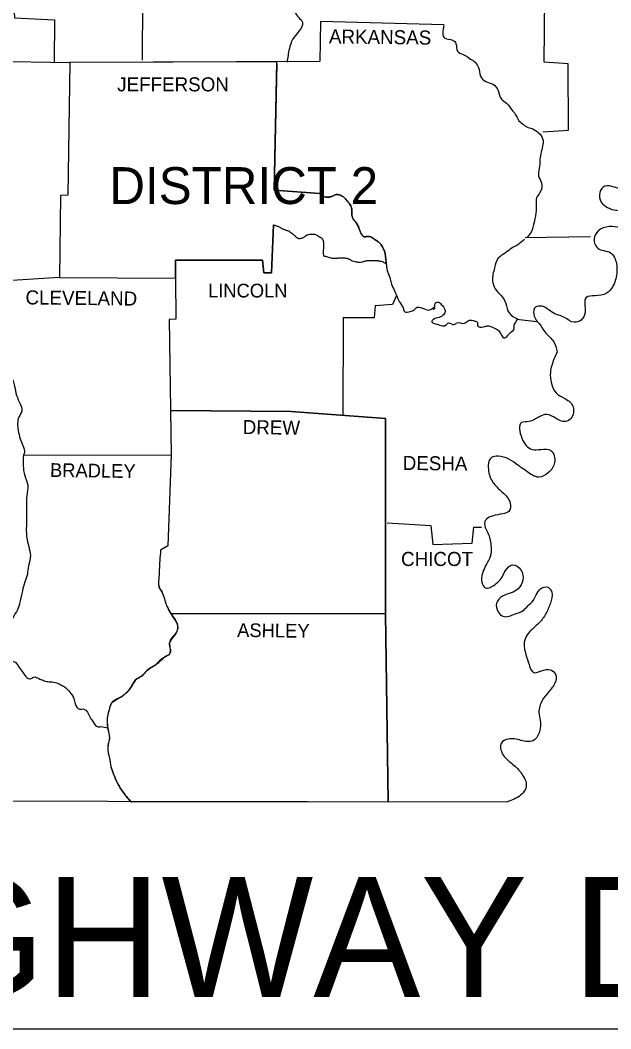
# Model space of a CAD drawing. Extents: x -2512 to 3792, y -435 to 2624.
# Drawn here: x 2982.2 to 3159.1, y 1364.9 to 1667 of the extents above; entities that cross this region are included whole.
import ezdxf

# ---------------------------------------------------------------- set-up
doc = ezdxf.new("R2010")
doc.units = 0
for name, color, linetype in [('1', 7, 'Continuous'), ('2', 7, 'Continuous'), ('3', 7, 'Continuous'), ('S_MISC_BOUNDARY', 7, 'Continuous')]:
    doc.layers.add(name, color=color, linetype=linetype)

msp = doc.modelspace()

# ---------------------------------------------------------------- linework, layer by layer
at = {"layer": '1'}
msp.add_line((3133.42, 1601.94), (3152.99, 1602.24), dxfattribs=at)
for points in [[(3007.21, 1732.56), (3012.88, 1732.17), (3012.98, 1694.79), (3007.89, 1673.56), (3018.75, 1673.07), (3018.66, 1655.07)], [(3138.71, 1633.54), (3146.34, 1634.03), (3146.24, 1653.9), (3139.1, 1654.38), (3139.49, 1693.23), (3133.33, 1694.11), (3133.13, 1720.23), (3216.59, 1720.82)], [(2931.68, 1708.1), (2942.63, 1707.41), (2942.24, 1695.18), (2955.06, 1694.69), (2955.26, 1684.03), (2961.32, 1683.54), (2961.32, 1681.68), (2967, 1681.29), (2967.19, 1674.44), (2980.11, 1674.44), (2980.5, 1667.69), (2992.44, 1667.1), (2992.34, 1654.38)], [(3109.06, 1665.64), (3072.08, 1666.61), (3071.88, 1654.58), (2997.03, 1654.29)], [(2940.68, 1641.37), (2946.16, 1642.15), (2946.55, 1645.48), (2949.78, 1646.07), (2949.97, 1648.02), (2972.77, 1648.71), (2973.65, 1654.68), (2997.03, 1654.29)], [(2997.03, 1654.09), (2996.45, 1614.56), (2994.2, 1614.47), (2993.9, 1589.91)], [(3059.06, 1653.99), (3058.28, 1616.13), (3071.88, 1615.05)], [(3057.99, 1605.66), (3057.4, 1591.28), (3055.15, 1591.28), (3054.76, 1595.09), (3028.73, 1595.09), (3028.73, 1589.61)], [(2993.9, 1589.91), (2979.62, 1589.03)], [(2993.9, 1589.91), (3028.54, 1589.71)], [(3028.73, 1589.71), (3028.83, 1577.48), (3026.78, 1577.38), (3027.36, 1536.78)], [(3094.87, 1584.53), (3093.7, 1581.88), (3088.51, 1581.4), (3088.22, 1577.87), (3078.93, 1577.87), (3078.83, 1548.62)], [(3105.83, 1580.22), (3106.13, 1580.51), (3106.42, 1580.81), (3106.42, 1580.81)], [(3027.07, 1550.09), (3063.37, 1549.79), (3091.55, 1547.64)], [(3091.55, 1547.64), (3091.55, 1489.13), (3092.33, 1432.87)], [(2983.14, 1536.68), (3027.36, 1536.78)], [(3027.36, 1536.78), (3026.39, 1509.58), (3024.23, 1508.21)], [(3092.04, 1516.43), (3105.15, 1515.65), (3105.73, 1509.97), (3117.57, 1510.36), (3118.06, 1515.16), (3120.31, 1515.16)], [(2769.26, 1512.61), (2769.46, 1433.46), (3128.04, 1432.87)], [(3027.95, 1489.23), (3091.55, 1489.23)]]:
    msp.add_lwpolyline(points, dxfattribs=at)
for points in [[(3210.42, 1697.14), (3208.17, 1694.3), (3204.85, 1696.06), (3204.85, 1698.41), (3205.34, 1700.86), (3204.16, 1702.42), (3202.11, 1701.74), (3202.11, 1698.71), (3201.91, 1695.77), (3201.32, 1691.56), (3202.69, 1690.29), (3205.83, 1689.9), (3208.08, 1689.31), (3209.45, 1687.06), (3209.35, 1684.32), (3208.27, 1681.68), (3206.71, 1679.53), (3204.26, 1678.75), (3202.3, 1680.02), (3201.52, 1682.56), (3200.64, 1684.81), (3198.98, 1686.48), (3197.22, 1684.62), (3196.82, 1681.19), (3196.92, 1678.26), (3196.92, 1674.25), (3199.47, 1671.6), (3201.03, 1668.57), (3200.54, 1665.83), (3198.68, 1662.6), (3197.9, 1659.77), (3197.12, 1655.95), (3197.22, 1651.74), (3196.53, 1647.63), (3195.16, 1644.89), (3192.62, 1642.64), (3190.95, 1641.18), (3189.58, 1639.71), (3188.9, 1636.77), (3188.41, 1634.72), (3186.55, 1632.27), (3185.08, 1632.08), (3183.91, 1633.05), (3183.52, 1634.72), (3183.52, 1636.38), (3182.74, 1638.04), (3180.29, 1638.73), (3178.33, 1638.63), (3177.45, 1637.26), (3178.72, 1633.45), (3179.21, 1631), (3178.53, 1627.67), (3178.92, 1627.28), (3175.4, 1625.42), (3172.56, 1625.13), (3170.21, 1624.44), (3167.96, 1622.98), (3166.88, 1620.82), (3165.32, 1619.06), (3163.95, 1617.4), (3162.09, 1616.62), (3160.04, 1617.01), (3157.3, 1617.3), (3155.73, 1615.35), (3156.22, 1612.51), (3158.08, 1610.85), (3160.82, 1610.06), (3163.66, 1610.26), (3166.4, 1610.55), (3168.94, 1609.18), (3168.45, 1606.54), (3166, 1605.27), (3162.38, 1604.88), (3159.45, 1605.17), (3155.93, 1604.39), (3154.17, 1602.14), (3155.14, 1598.71), (3158.96, 1597.34), (3160.72, 1594.11), (3160.82, 1591.08), (3159.55, 1587.07), (3157.79, 1585.21), (3154.36, 1584.43), (3151.72, 1583.94), (3151.33, 1579.44), (3150.15, 1577.19), (3148.1, 1576.5), (3145.16, 1577.97), (3143.4, 1578.66), (3141.25, 1579.63), (3138.51, 1581.3), (3136.46, 1581), (3137.04, 1576.7), (3137.24, 1576.5), (3139.59, 1573.27), (3141.94, 1570.73), (3143.01, 1567.7)], [(3059.95, 1681.68), (3062.39, 1680.02), (3064.93, 1678.06), (3065.62, 1675.42), (3065.42, 1673.56), (3064.64, 1672), (3064.45, 1669.55), (3065.62, 1667.79), (3066.7, 1666.32), (3065.62, 1663.68), (3063.76, 1661.23), (3062.78, 1658.49), (3062.1, 1654.38)], [(3109.06, 1665.64), (3109.35, 1661.62), (3111.7, 1661.04), (3112.68, 1659.96), (3113.17, 1657.71), (3114.83, 1656.73), (3117.08, 1655.36), (3118.45, 1654.38), (3119.43, 1652.82), (3120.02, 1650.27), (3121.58, 1648.61), (3123.74, 1647.83), (3125.3, 1645.97), (3126.28, 1643.33), (3127.85, 1642.15), (3129.41, 1640.1), (3130.19, 1639.22), (3131.56, 1636.87), (3132.93, 1635.7), (3133.91, 1635.01), (3135.48, 1634.52), (3137.43, 1633.25), (3138.71, 1631.29), (3138.71, 1629.83), (3138.22, 1627.58), (3137.83, 1625.23), (3137.63, 1622.59), (3137.43, 1620.24), (3138.32, 1618.28), (3137.83, 1615.35), (3136.85, 1613.78), (3136.75, 1611.63), (3136.46, 1608.4), (3136.07, 1606.54), (3135.18, 1603.51), (3133.91, 1601.94)], [(3071.88, 1615.05), (3073.35, 1614.07), (3075.4, 1614.17), (3076.77, 1614.76), (3077.85, 1614.66), (3079.32, 1613.78), (3080.3, 1612.61), (3080.98, 1611.73), (3081.47, 1610.36), (3081.47, 1609.08), (3081.96, 1607.32), (3082.55, 1606.64), (3083.33, 1605.37), (3083.82, 1604.19), (3084.11, 1603.41), (3085.19, 1602.14), (3086.17, 1602.24), (3087.05, 1602.14), (3088.22, 1601.45), (3089.98, 1600.08), (3090.28, 1599.69), (3091.45, 1597.15), (3091.65, 1595.58), (3091.84, 1593.53), (3092.23, 1591.57), (3093.02, 1589.42), (3093.41, 1587.95), (3094.29, 1585.9), (3094.87, 1584.53), (3095.66, 1582.76), (3096.83, 1580.81), (3097.32, 1579.63), (3098.98, 1579.73), (3100.16, 1580.22), (3101.04, 1581), (3102.11, 1580.91), (3103.29, 1580.51), (3104.85, 1580.22), (3105.83, 1580.81), (3106.32, 1581.2), (3106.42, 1582.08), (3107.3, 1582.57), (3108.28, 1581.88), (3109.35, 1580.32), (3109.35, 1579.34), (3108.96, 1578.75), (3107.69, 1577.97), (3105.93, 1577.38), (3105.44, 1576.7), (3107.1, 1575.92), (3109.75, 1575.72), (3110.43, 1576.31), (3112.19, 1575.82), (3112.88, 1576.31), (3115.23, 1576.21), (3116.3, 1576.99), (3118.45, 1576.89), (3119.14, 1576.41), (3119.14, 1575.52), (3120.9, 1575.13), (3122.17, 1575.43), (3123.84, 1574.94), (3125.3, 1574.15), (3126.09, 1573.08), (3127.06, 1571.9), (3127.94, 1572.2), (3128.63, 1573.08), (3130.1, 1574.64), (3130.1, 1575.62), (3130.49, 1576.31), (3130.98, 1577.29)], [(3133.23, 1601.35), (3131.17, 1599.69), (3129.41, 1598.71), (3127.55, 1597.34), (3125.3, 1595.68), (3124.23, 1592.84), (3123.64, 1588.93), (3124.42, 1586.58), (3126.18, 1584.53), (3127.36, 1582.86), (3128.24, 1579.93), (3130.39, 1577.87), (3131.08, 1577.58)], [(2965.24, 1575.92), (2967.49, 1574.45), (2969.34, 1572.49), (2970.71, 1571.02), (2971.59, 1569.36), (2972.77, 1567.4), (2974.43, 1563.69), (2975.9, 1562.41), (2977.95, 1561.14), (2979.23, 1560.26), (2980.5, 1557.42), (2981.09, 1554.59), (2982.16, 1552.04), (2982.65, 1550.09), (2981.77, 1548.13), (2981.57, 1544.22), (2982.16, 1541.57), (2982.94, 1539.62), (2983.43, 1537.37), (2983.14, 1536.68)], [(3143.01, 1567.7), (3142.03, 1565.45), (3140.96, 1561.53), (3141.25, 1558.21), (3142.72, 1555.37), (3145.07, 1553.8), (3147.61, 1551.55), (3147.41, 1548.13), (3145.95, 1546.86), (3142.52, 1547.74), (3139.88, 1548.91), (3137.63, 1548.23), (3134.6, 1546.76), (3132.35, 1546.47), (3132.45, 1541.77), (3135.48, 1538.44), (3138.12, 1538.44), (3141.15, 1538.05), (3142.23, 1534.53), (3140.47, 1531.59), (3137.53, 1530.13), (3133.81, 1531.89), (3131.17, 1533.75), (3128.53, 1535.51), (3125.2, 1536.39), (3123.35, 1536), (3122.47, 1531.89), (3124.03, 1528.17), (3126.57, 1525.63), (3128.92, 1522.3), (3128.53, 1519.85), (3126.77, 1519.17), (3123.64, 1518.48), (3121.78, 1517.51), (3121.29, 1516.72), (3122.27, 1513.4), (3123.15, 1509.78), (3123.15, 1507.04), (3122.07, 1504.49), (3120.41, 1500.58), (3120.61, 1498.03), (3121.78, 1496.86), (3123.25, 1497.25), (3125.2, 1498.62), (3126.48, 1500.19), (3127.55, 1502.14), (3129.61, 1503.81), (3132.15, 1502.34), (3132.74, 1499.31), (3131.27, 1496.67), (3129.22, 1495.49), (3126.67, 1494.51), (3124.81, 1492.36), (3125.3, 1489.82), (3126.77, 1488.45), (3130.39, 1489.13), (3132.84, 1490.21), (3134.21, 1491.58), (3135.87, 1493.24), (3136.75, 1494.9), (3138.02, 1496.67), (3140.27, 1497.15), (3141.35, 1495.69), (3140.96, 1492.36), (3139.59, 1489.23), (3137.73, 1486.59), (3135.67, 1484.73), (3133.13, 1480.72), (3133.62, 1477), (3134.6, 1473.97), (3135.97, 1471.62), (3138.32, 1472.11), (3140.96, 1472.4), (3142.52, 1471.13), (3142.33, 1468.39), (3140.37, 1465.75), (3138.51, 1463.2), (3137.53, 1459.68), (3137.92, 1457.24), (3137.92, 1454.98), (3137.14, 1452.54), (3135.77, 1451.17), (3132.15, 1451.27), (3128.34, 1451.66), (3126.28, 1450.48), (3126.67, 1447.16), (3128.92, 1444.71), (3130.49, 1443.44), (3132.74, 1440.7), (3133.72, 1438.45), (3133.42, 1436.49), (3132.05, 1434.83), (3128.04, 1432.87)], [(2983.14, 1536.68), (2983.53, 1530.62), (2984.41, 1527.68), (2984.12, 1524.55), (2984.02, 1521.52), (2984.02, 1518.78), (2984.02, 1516.14), (2984.02, 1513.4), (2984.22, 1511.44), (2984.9, 1508.6), (2985.19, 1505.96), (2984.61, 1503.42), (2984.31, 1501.07), (2983.53, 1498.72), (2982.85, 1496.08), (2982.06, 1492.65), (2981.38, 1490.4), (2980.01, 1488.06), (2979.13, 1485.9), (2977.76, 1484.53), (2977.56, 1482.18), (2977.86, 1480.03), (2977.66, 1478.08), (2978.35, 1476.22), (2980.11, 1474.94)], [(3024.23, 1508.21), (3023.94, 1505.18), (3023.84, 1502.34), (3023.65, 1499.6), (3023.65, 1497.55), (3024.82, 1495.3), (3025.51, 1493.14), (3026.19, 1491.28), (3027.56, 1488.84), (3028.83, 1486.98), (3029.22, 1484.34), (3028.44, 1482.97), (3026.97, 1480.91), (3026.87, 1477.19), (3025.11, 1476.02), (3022.86, 1474.06), (3021.59, 1473.18), (3020.22, 1472.3), (3018.75, 1470.74), (3016.6, 1469.27), (3015.04, 1466.82), (3013.28, 1464.96), (3011.81, 1463.99), (3009.75, 1462.71), (3008.87, 1460.76), (3008.19, 1457.14), (3008.48, 1454.5), (3008.87, 1452.15), (3008.38, 1449.21), (3008.87, 1445.98), (3009.36, 1443.44), (3010.14, 1441.19), (3011.22, 1438.65), (3012.59, 1436.3), (3015.53, 1432.68)], [(2926.69, 1485.61), (2928.25, 1486.69), (2929.72, 1487.27), (2931.19, 1486.98), (2932.75, 1486.78), (2934.12, 1486.98), (2935.88, 1486.69), (2937.35, 1485.8), (2939.01, 1485.12), (2940.68, 1485.12), (2942.14, 1485.12), (2943.42, 1484.24), (2945.77, 1484.34), (2947.72, 1485.12), (2949.68, 1485.71), (2952.32, 1486), (2954.67, 1484.34), (2956.33, 1482.97), (2957.7, 1481.4), (2958.68, 1479.64), (2959.76, 1478.66), (2961.52, 1477.98), (2962.89, 1477.68), (2964.55, 1477.19), (2965.43, 1476.8), (2966.21, 1474.94), (2967.49, 1472.4), (2969.93, 1471.52), (2972.96, 1472.69), (2975.41, 1473.38), (2977.17, 1473.97), (2978.25, 1474.36), (2979.23, 1474.46), (2978.93, 1474.65), (2980.11, 1474.94), (2981.18, 1474.16), (2981.87, 1473.09), (2983.04, 1471.52), (2984.12, 1470.15), (2985.19, 1469.66), (2986.27, 1470.25), (2987.74, 1469.76), (2989.01, 1469.27), (2990.48, 1468.88), (2991.75, 1468.78), (2993.41, 1468.39), (2994.69, 1467.7), (2995.86, 1467.02), (2997.03, 1465.75), (2998.21, 1463.79), (2998.6, 1462.23), (2999.97, 1460.66), (3001.24, 1460.66), (3003.1, 1458.12), (3003.78, 1457.14), (3005.25, 1455.38), (3006.33, 1455.38), (3008.38, 1454.98)]]:
    msp.add_spline(points, degree=3, dxfattribs=at)
at = {"layer": '2'}
msp.add_line((2628.58, 1364.87), (3283.1, 1364.87), dxfattribs=at)
at = {"layer": '3'}
msp.add_line((3130.78, 1577.48), (3136.95, 1576.7), dxfattribs=at)
at = {"layer": 'S_MISC_BOUNDARY'}
for p, q in [((3059.08, 1654.53), (2997.03, 1654.29)), ((2993.9, 1589.91), (3028.73, 1589.71)), ((3027.17, 1550.09), (3027.36, 1536.78)), ((3091.55, 1489.23), (3091.55, 1547.64)), ((3027.32, 1489.23), (3091.55, 1489.23)), ((3091.55, 1489.13), (3027.32, 1489.13)), ((3092.33, 1432.83), (3091.55, 1489.13)), ((3015.17, 1432.96), (3092.33, 1432.83))]:
    msp.add_line(p, q, dxfattribs=at)
for points in [[(2997.03, 1654.29), (2996.45, 1614.56), (2994.2, 1614.47), (2993.9, 1589.91)], [(3071.88, 1615.05), (3058.28, 1616.13), (3059.08, 1654.53)], [(3028.73, 1589.71), (3028.73, 1595.09), (3054.76, 1595.09), (3055.15, 1591.28), (3057.4, 1591.28), (3057.99, 1605.66)], [(3091.55, 1547.64), (3063.37, 1549.79), (3027.17, 1550.09)], [(3027.36, 1536.78), (3026.39, 1509.58), (3024.23, 1508.21)]]:
    msp.add_lwpolyline(points, dxfattribs=at)
for points in [[(3082.83, 1606.23), (3082.55, 1606.64), (3082.41, 1606.81), (3082.25, 1606.97), (3082.09, 1607.14), (3081.96, 1607.32), (3081.62, 1608.18), (3081.47, 1609.08), (3081.46, 1609.4), (3081.48, 1609.72), (3081.49, 1610.04), (3081.47, 1610.36), (3081.4, 1610.72), (3081.3, 1611.07), (3080.98, 1611.73), (3080.3, 1612.61), (3079.32, 1613.78), (3078.64, 1614.3), (3078.26, 1614.5), (3077.85, 1614.66), (3077.31, 1614.78), (3077.04, 1614.79), (3076.77, 1614.76), (3076.43, 1614.65), (3076.09, 1614.48), (3075.75, 1614.3), (3075.4, 1614.17), (3074.38, 1613.98), (3073.86, 1613.98), (3073.35, 1614.07), (3072.94, 1614.24), (3072.56, 1614.46), (3071.88, 1615.05)], [(3057.99, 1605.66), (3058.44, 1605.56), (3058.89, 1605.43), (3059.75, 1605.07), (3060.07, 1604.91), (3060.39, 1604.73), (3060.7, 1604.55), (3061.02, 1604.39), (3061.43, 1604.23), (3061.86, 1604.11), (3062.28, 1603.98), (3062.68, 1603.8), (3063.24, 1603.43), (3063.76, 1603.02), (3064.13, 1602.7), (3064.49, 1602.37), (3064.85, 1602.04), (3065.03, 1601.89), (3065.23, 1601.75), (3065.63, 1601.61), (3066.09, 1601.64), (3066.56, 1601.77), (3066.99, 1601.94), (3067.31, 1602.13), (3067.61, 1602.35), (3067.92, 1602.57), (3068.26, 1602.72), (3069.53, 1602.92), (3070.24, 1602.91)], [(3057.99, 1605.66), (3058.44, 1605.56), (3058.89, 1605.43), (3059.75, 1605.07), (3060.07, 1604.91), (3060.39, 1604.73), (3060.7, 1604.55), (3061.02, 1604.39), (3061.43, 1604.23), (3061.86, 1604.11), (3062.28, 1603.98), (3062.68, 1603.8), (3063.24, 1603.43), (3063.76, 1603.02), (3064.13, 1602.7), (3064.49, 1602.37), (3064.85, 1602.04), (3065.03, 1601.89), (3065.23, 1601.75), (3065.63, 1601.61), (3066.09, 1601.64), (3066.56, 1601.77), (3066.99, 1601.94), (3067.31, 1602.13), (3067.61, 1602.35), (3067.92, 1602.57), (3068.26, 1602.72), (3069.53, 1602.92), (3070.24, 1602.91)], [(3091.8, 1593.99), (3091.65, 1595.58), (3091.56, 1596.37), (3091.51, 1596.76), (3091.45, 1597.15), (3090.99, 1598.46), (3090.65, 1599.08), (3090.28, 1599.69), (3089.98, 1600.08), (3089.78, 1600.28), (3089.57, 1600.47), (3089.14, 1600.81), (3088.22, 1601.45), (3087.66, 1601.83), (3087.36, 1602), (3087.21, 1602.07), (3087.05, 1602.14), (3086.61, 1602.22), (3086.17, 1602.24), (3085.92, 1602.21), (3085.68, 1602.15), (3085.43, 1602.1), (3085.19, 1602.14), (3084.99, 1602.23), (3084.82, 1602.35), (3084.52, 1602.66), (3084.4, 1602.84), (3084.29, 1603.02), (3084.11, 1603.41), (3083.82, 1604.19), (3083.33, 1605.37), (3082.96, 1606.02), (3082.83, 1606.23)], [(3070.24, 1602.91), (3070.51, 1602.82), (3071.59, 1602.24), (3071.75, 1602.14), (3072.23, 1601.87), (3072.52, 1601.65), (3072.65, 1601.52), (3072.71, 1601.44), (3072.76, 1601.35), (3072.95, 1600.73), (3072.96, 1600.4), (3072.96, 1600.08), (3072.96, 1598.62), (3072.96, 1596.56), (3073.03, 1596.42), (3073.21, 1596.35), (3073.54, 1596.29), (3073.64, 1596.27), (3074.25, 1596.08), (3074.86, 1595.89), (3076.09, 1595.68), (3076.5, 1595.69), (3076.92, 1595.72), (3077.34, 1595.75), (3077.75, 1595.78), (3078.53, 1595.79), (3078.63, 1595.79)], [(3070.24, 1602.91), (3070.51, 1602.82), (3071.59, 1602.24), (3071.75, 1602.14), (3072.23, 1601.87), (3072.52, 1601.65), (3072.65, 1601.52), (3072.71, 1601.44), (3072.76, 1601.35), (3072.95, 1600.73), (3072.96, 1600.4), (3072.96, 1600.08), (3072.96, 1598.62), (3072.96, 1596.56), (3073.03, 1596.42), (3073.21, 1596.35), (3073.54, 1596.29), (3073.64, 1596.27), (3074.25, 1596.08), (3074.86, 1595.89), (3076.09, 1595.68), (3076.5, 1595.69), (3076.92, 1595.72), (3077.34, 1595.75), (3077.75, 1595.78), (3078.53, 1595.79), (3078.63, 1595.79)], [(3078.63, 1595.79), (3079.32, 1595.78), (3079.96, 1595.68), (3080.28, 1595.59), (3080.59, 1595.48), (3080.87, 1595.35), (3081.13, 1595.18), (3081.39, 1595.02), (3081.67, 1594.9), (3082.45, 1594.7), (3083.62, 1594.51), (3084.6, 1594.6), (3085.02, 1594.71), (3085.43, 1594.84), (3085.84, 1594.95), (3086.26, 1595), (3087.24, 1595), (3088.81, 1595), (3089.3, 1594.97), (3089.54, 1594.93), (3089.79, 1594.9), (3090.84, 1594.58), (3091.8, 1593.99)], [(3078.63, 1595.79), (3079.32, 1595.78), (3079.96, 1595.68), (3080.28, 1595.59), (3080.59, 1595.48), (3080.87, 1595.35), (3081.13, 1595.18), (3081.39, 1595.02), (3081.67, 1594.9), (3082.45, 1594.7), (3083.62, 1594.51), (3084.6, 1594.6), (3085.02, 1594.71), (3085.43, 1594.84), (3085.84, 1594.95), (3086.26, 1595), (3087.24, 1595), (3088.81, 1595), (3089.3, 1594.97), (3089.54, 1594.93), (3089.79, 1594.9), (3090.84, 1594.58), (3091.8, 1593.99)], [(3024.23, 1508.21), (3023.94, 1505.18), (3023.84, 1502.34), (3023.65, 1499.6), (3023.59, 1498.57), (3023.6, 1498.06), (3023.65, 1497.55), (3023.84, 1496.95), (3024.18, 1496.4), (3024.54, 1495.87), (3024.82, 1495.3), (3025.51, 1493.14), (3026.19, 1491.28), (3027.32, 1489.23)], [(3027.32, 1489.13), (3027.56, 1488.74), (3027.87, 1488.27), (3028.19, 1487.81), (3028.52, 1487.36), (3028.83, 1486.88), (3029.33, 1485.57), (3029.37, 1484.88), (3029.22, 1484.24), (3028.44, 1482.87), (3028.08, 1482.35), (3027.7, 1481.84), (3027.33, 1481.33), (3026.97, 1480.81), (3026.81, 1479.92), (3027.02, 1478.9), (3027.18, 1477.9), (3026.88, 1477.1), (3026.67, 1476.92), (3026.46, 1476.77), (3026, 1476.49), (3025.54, 1476.23), (3025.12, 1475.92), (3024.01, 1474.93), (3023.45, 1474.43), (3022.86, 1473.97), (3021.59, 1473.09), (3020.22, 1472.2), (3019.82, 1471.86), (3019.54, 1471.54)], [(3019.54, 1471.54), (3019.47, 1471.45), (3019.12, 1471.03), (3018.76, 1470.64), (3018.23, 1470.26), (3017.66, 1469.93), (3017.1, 1469.59), (3016.6, 1469.17), (3016.17, 1468.6), (3015.8, 1467.96), (3015.45, 1467.32), (3015.04, 1466.73), (3014.63, 1466.23), (3014.21, 1465.74), (3013.28, 1464.87), (3011.81, 1463.89), (3011.3, 1463.58), (3010.78, 1463.28), (3010, 1462.8), (3009.75, 1462.62), (3009.4, 1462.22), (3009.17, 1461.73), (3008.87, 1460.66), (3008.61, 1459.76), (3008.38, 1458.86), (3008.22, 1457.95), (3008.19, 1457.04), (3008.31, 1455.72), (3008.48, 1454.4), (3008.58, 1453.79)], [(3008.58, 1453.79), (3008.87, 1452.05), (3008.83, 1451.32), (3008.63, 1450.58), (3008.43, 1449.85), (3008.38, 1449.11), (3008.87, 1445.89), (3009.36, 1443.34), (3010.15, 1441.09), (3011.22, 1438.55), (3011.86, 1437.35), (3012.59, 1436.2), (3013.82, 1434.53), (3015.17, 1432.96)]]:
    msp.add_spline(points, degree=3, dxfattribs=at)

# ---------------------------------------------------------------- texts
at = {"layer": '2'}
for s, height, rotation, p in [('ARKANSAS', 4.206, 359.2678, (3074.62, 1660.06)), ('CLEVELAND', 4.207, 359.3377, (2983.73, 1581.88)), ('DREW', 4.206, 359.2258, (3048.79, 1543.04)), ('DESHA', 4.206, 359.3704, (3096.73, 1532.28)), ('BRADLEY', 4.108, 359.1449, (2991.07, 1530.22)), ('ASHLEY', 4.109, 359.2361, (3047.13, 1482.28))]:
    msp.add_text(s, height=height, rotation=rotation, dxfattribs=at).set_placement(p)
for s, height, p in [('JEFFERSON', 4.207, (3011.22, 1645.68)), ('LINCOLN', 4.109, (3038.42, 1583.94)), ('CHICOT', 4.207, (3096.24, 1503.51)), ('ARKANSAS HIGHWAY DISTRICT 2', 36, (2628.58, 1374.37))]:
    msp.add_text(s, height=height, dxfattribs=at).set_placement(p)
at = {"layer": '3'}
msp.add_text('DISTRICT 2', height=11.056, dxfattribs=at).set_placement((3008.87, 1611.92))

doc.saveas('drawing.dxf')
